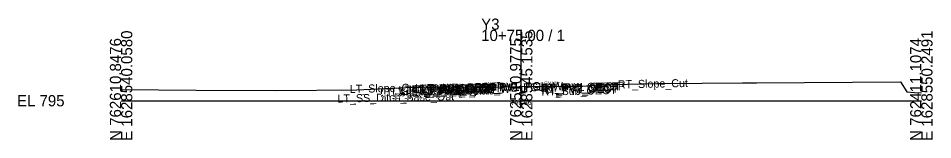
# Model space of a CAD drawing. Extents: x -26 to 203, y -10 to 3017.
# Drawn here: x -25.7 to 202.8, y 1490.3 to 1520.5 of the extents above; entities that cross this region are included whole.
import ezdxf

# ---------------------------------------------------------------- set-up
doc = ezdxf.new("R2010")
doc.units = 0
for name, color, linetype in [('Default', 7, 'Continuous'), ('Exist Cross Section Cell', 7, 'Continuous'), ('Exist XS Center Line Elevation Label', 7, 'Continuous'), ('Exist XS Ground Line', 7, 'Continuous'), ('Prop CMT Shld Paved Course 1', 7, 'Continuous'), ('Prop XS SE Text', 7, 'Continuous'), ('Scratch_Level_0', 7, 'Continuous')]:
    doc.layers.add(name, color=color, linetype=linetype)

msp = doc.modelspace()

# ---------------------------------------------------------------- linework, layer by layer
at = {"layer": 'Exist Cross Section Cell'}
for p, q in [((100, 1500), (100, 1517.67)), ((0, 1500), (100, 1500)), ((100, 1500), (200, 1500))]:
    msp.add_line(p, q, dxfattribs=at)
at = {"layer": 'Exist XS Ground Line'}
msp.add_lwpolyline([(0, 1502.76), (18.77, 1502.65), (38.83, 1502.54), (58.93, 1502.75), (72.94, 1503.39), (75.26, 1503.4), (76.5, 1503.44), (84.79, 1503.36), (85.17, 1503.18), (95.56, 1503.45), (99.46, 1503.55), (100, 1503.56), (110.69, 1503.6), (115.35, 1503.6), (119.26, 1503.96), (133.88, 1504.26), (135.18, 1504.28), (155.33, 1504.47), (156.25, 1504.47), (157.79, 1504.47), (158.82, 1504.48), (194.81, 1504.68), (196.41, 1502.23), (198.29, 1502.06), (200, 1501.97)], dxfattribs=at)
at = {"layer": 'Prop CMT Shld Paved Course 1'}
msp.add_lwpolyline([(85, 1503.3), (85, 1503.3)], dxfattribs=at)

# ---------------------------------------------------------------- texts
at = {"layer": 'Default'}
msp.add_text('-', height=0.0001, dxfattribs=at).set_placement((0, 1500))
at = {"layer": 'Exist Cross Section Cell'}
for s, p in [('Y3', (90, 1517.67)), ('10+75.00 / 1', (90, 1514.87)), ('EL 795', (-26, 1498.6))]:
    msp.add_text(s, height=2.8, dxfattribs=at).set_placement(p)
for s, p in [('N 762610.8476', (0, 1490)), ('E 1628540.0580', (2.8, 1490)), ('N 762510.9775', (100, 1490)), ('E 1628545.1535', (102.8, 1490)), ('N 762411.1074', (200, 1490)), ('E 1628550.2491', (202.8, 1490))]:
    msp.add_text(s, height=2.8, rotation=90, dxfattribs=at).set_placement(p)
at = {"layer": 'Exist XS Center Line Elevation Label'}
msp.add_text('798.56', height=1.2, dxfattribs=at).set_placement((97.48, 1498.96))
at = {"layer": 'Prop XS SE Text'}
for rotation, p in [(1.0026, (90.74, 1503.57)), (359.4271, (105.71, 1503.74))]:
    msp.add_text('EXIST.', height=1, rotation=rotation, dxfattribs=at).set_placement(p)
at = {"layer": 'Scratch_Level_0'}
for s, p in [('LT_Slope_Cut', (57.17, 1501.94)), ('LT_GS_OS_CTL', (69.39, 1501.69)), ('LT_PS3_Shelf_Out', (69.91, 1501.41)), ('LT_PV2_OEEOP_W', (72.61, 1501.8)), ('LT_PV3_OEEOP_W', (72.61, 1501.47)), ('LT_PV1_OEEOP_W', (73.17, 1501.94)), ('LT_PS3_OEOP', (74.66, 1501.51)), ('LT_PS2_OEOP', (75, 1501.85)), ('LT_PV1_OEEOP', (75.06, 1502.1)), ('LT_PV2_OEOT', (75.2, 1501.85)), ('LT_PV3_OEOT', (75.2, 1501.52)), ('LT_PV1_OEOT', (75.76, 1502.11)), ('LT_PS1_OEOP', (75.83, 1502.11)), ('LT_PV1_PGL_W', (89.91, 1502.23)), ('PV2_PGL', (93.93, 1502.19)), ('PV1_PGL', (94.49, 1502.45)), ('RT_PV1_OEEOP', (104.85, 1502.21)), ('RT_PV2_OEOT', (105.15, 1501.96)), ('RT_PV3_OEOT', (105.15, 1501.63)), ('RT_PV1_OEOT', (105.71, 1502.22)), ('RT_Slope_Cut', (124.14, 1503.07)), ('LT_SS_Ditch_Base_Out', (54.1, 1499.54)), ('LT_Sub_OSS_DLT', (64.74, 1500.98)), ('LT_Sub_Trench_Out', (67.79, 1501.04)), ('LT_Sub_OEOT', (75.1, 1501.18)), ('RT_Sub_OEOT', (105.05, 1501.29))]:
    msp.add_text(s, height=2, rotation=1.1458, dxfattribs=at).set_placement(p)

doc.saveas('drawing.dxf')
